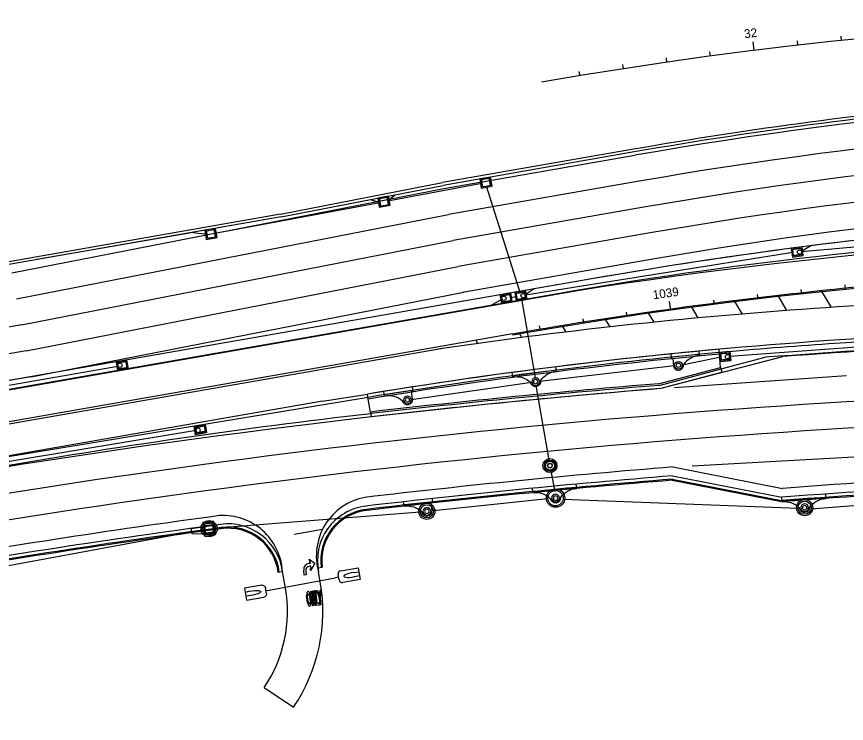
# Model space of a CAD drawing. Extents: x 468143 to 491361, y 1438528 to 1468730.
# Drawn here: x 485954.6 to 486331.8, y 1467266.4 to 1467587.8 of the extents above; entities that cross this region are included whole.
import ezdxf

# ---------------------------------------------------------------- set-up
doc = ezdxf.new("R2010")
doc.units = 0
doc.layers.add('Default', color=7, linetype='Continuous')
doc.layers.add('Xreference_dp', color=7, linetype='Continuous')

# ---------------------------------------------------------------- blocks, each defined once
blk = doc.blocks.new('POINT_DISPLAY')
at = {"layer": 'Default'}
blk.add_line((0, 0), (0, 0), dxfattribs=at)
blk = doc.blocks.new('InltCurb2_35')
at = {"layer": 'Default'}
for p, q in [((-10, 2), (-10, 0)), ((-10, 1.5), (10, 1.5)), ((10, 2), (10, 0))]:
    blk.add_line(p, q, dxfattribs=at)
for radius in [1.75, 1]:
    blk.add_circle((0, 5.5), radius, dxfattribs=at)
for centre, radius, start, end in [((0, 5.5), 2.25, 0, 180), ((-9.85, 12), 10, 269.1432, 319.4677), ((9.85, 12), 10, 220.5323, 270.8568)]:
    blk.add_arc(centre, radius, start, end, dxfattribs=at)
for p in [(0, 7.75), (-1.75, 5.5), (-1.75, 5.5), (-1.62, 4.84), (-1.6, 6.2), (-1.26, 4.28), (-1.22, 6.76), (-0.7, 3.9), (-0.66, 7.12), (0, 7.25), (0, 7.25), (0, 5.5), (0, 5.5), (0.66, 3.88), (0.7, 7.1), (1.22, 4.24), (1.26, 6.72), (1.6, 4.8), (1.62, 6.16), (1.75, 5.5), (1.75, 5.5), (0, 3.75), (0, 3.75), (0, 0), (0, 0)]:
    blk.add_blockref('POINT_DISPLAY', p, dxfattribs=at)
blk = doc.blocks.new('InltCurb7_40')
at = {"layer": 'Default'}
for p, q in [((2.5, 4), (-2.5, 4)), ((-2.5, 4), (-2.5, 0)), ((2.5, 0), (2.5, 4)), ((2.5, 3.25), (-2.5, 3.25)), ((-2.5, 0.75), (2.5, 0.75)), ((-2.5, 0), (2.5, 0))]:
    blk.add_line(p, q, dxfattribs=at)
blk.add_lwpolyline([(-2, 0.5), (2, 0.5), (2, 3.5), (-2, 3.5)], close=True, dxfattribs=at)
blk.add_circle((-1.04, 2.19), 1, dxfattribs=at)
for p in [(0, 4), (-2, 3.5), (-2, 2), (-2, 2), (-2, 0.5), (0, 3.5), (0, 3.5), (0, 2), (0, 2), (0, 0.5), (0, 0.5), (0, 0), (0, 0), (2, 3.5), (2, 2), (2, 2), (2, 0.5)]:
    blk.add_blockref('POINT_DISPLAY', p, dxfattribs=at)
blk = doc.blocks.new('InltCurb1_35')
at = {"layer": 'Default'}
for p, q in [((2.25, 2), (2.25, 5.5)), ((-10, 2), (-10, 0)), ((-10, 1.5), (3, 1.5)), ((3, 2), (2.25, 2)), ((3, 0), (3, 2))]:
    blk.add_line(p, q, dxfattribs=at)
for radius in [1.75, 1]:
    blk.add_circle((0, 5.5), radius, dxfattribs=at)
for centre, radius, start, end in [((0, 5.5), 2.25, 0, 180), ((-9.85, 12), 10, 269.1432, 319.4677)]:
    blk.add_arc(centre, radius, start, end, dxfattribs=at)
for p in [(0, 7.75), (-1.75, 5.5), (-1.75, 5.5), (-1.62, 4.84), (-1.6, 6.2), (-1.26, 4.28), (-1.22, 6.76), (-0.7, 3.9), (-0.66, 7.12), (0, 7.25), (0, 7.25), (0, 5.5), (0, 5.5), (0.66, 3.88), (0.7, 7.1), (1.22, 4.24), (1.26, 6.72), (1.6, 4.8), (1.62, 6.16), (1.75, 5.5), (1.75, 5.5), (0, 3.75), (0, 3.75), (0, 0), (0, 0)]:
    blk.add_blockref('POINT_DISPLAY', p, dxfattribs=at)
blk = doc.blocks.new('InltCurb5')
at = {"layer": 'Default'}
for p, q in [((-2.25, 3.5), (-8, 2.5)), ((-8, 2.5), (-8, 0)), ((-8, 1.5), (2.5, 1.5)), ((-8, 0), (2.5, 0)), ((2.25, 3.5), (-2.25, 3.5)), ((-1.96, 0), (-1.96, 1.5)), ((1.95, 0), (1.95, 1.5)), ((2.25, 2), (2.25, 3.5)), ((2.5, 2), (2.25, 2)), ((2.5, 0), (2.5, 2))]:
    blk.add_line(p, q, dxfattribs=at)
blk.add_lwpolyline([(-1.75, -0.5), (1.75, -0.5), (1.75, 3), (-1.75, 3)], close=True, dxfattribs=at)
for p in [(-1.75, 3), (-1.75, 1.25), (-1.75, 1.25), (0, 3.5), (0, 3), (0, 3), (0, 1.25), (0, 1.25), (1.75, 3), (1.75, 1.25), (1.75, 1.25), (-1.75, -0.5), (0, 0), (0, 0), (0, -0.5), (0, -0.5), (1.75, -0.5)]:
    blk.add_blockref('POINT_DISPLAY', p, dxfattribs=at)
blk = doc.blocks.new('InltBarwll')
at = {"layer": 'Default'}
for p, q in [((2.5, 0), (-2.5, 0)), ((-2.5, 0), (-2.5, -4.25)), ((-2.17, 0), (-2.17, -3.75)), ((-1.83, 0), (-1.83, -3.75)), ((1.83, -3.75), (1.83, 0)), ((2.17, -3.75), (2.17, 0)), ((2.5, -4.25), (2.5, 0)), ((-2.17, -3.75), (2.17, -3.75)), ((1.83, -0.5), (-1.83, -0.5)), ((-2.5, -4.25), (2.5, -4.25))]:
    blk.add_line(p, q, dxfattribs=at)
for p in [(0, 0), (0, 0), (-1.83, -0.5), (-1.83, -2.12), (-1.83, -2.12), (-1.83, -3.75), (0, -0.5), (0, -0.5), (0, -2.12), (0, -2.12), (0, -3.75), (0, -3.75), (1.83, -0.5), (1.83, -2.12), (1.83, -2.12), (1.83, -3.75), (0, -4.25)]:
    blk.add_blockref('POINT_DISPLAY', p, dxfattribs=at)
blk = doc.blocks.new('MESC24RCP4S')
at = {"layer": 'Default'}
for p, q in [((0, 2.45), (0, 3.97)), ((-2.75, -7.03), (-2.75, 0.95)), ((-1.25, 2.45), (1.25, 2.45)), ((2.75, 0.95), (2.75, -7.03)), ((2.75, -7.03), (-2.75, -7.03)), ((-0.98, -4.81), (-0.87, -7.03)), ((0.98, -4.8), (0.86, -7.03))]:
    blk.add_line(p, q, dxfattribs=at)
for centre, start, end in [((-1.25, 0.95), 90, 180), ((1.25, 0.95), 0, 90)]:
    blk.add_arc(centre, 1.5, start, end, dxfattribs=at)
blk.add_ellipse((0, -4), major_axis=(0, 4), ratio=0.25, start_param=4.509879, end_param=8.057799, dxfattribs=at)
for p in [(0, 3.97), (0, 2.45), (0, 0), (0, 0), (0, -7.03)]:
    blk.add_blockref('POINT_DISPLAY', p, dxfattribs=at)
blk = doc.blocks.new('JBottom60Dia')
at = {"layer": 'Default'}
for radius in [3.67, 3, 3]:
    blk.add_circle((0, 0), radius, dxfattribs=at)
for p in [(-2.75, 1.21), (-2.09, 2.15), (-1.13, 2.78), (0, 3), (0, 3), (0, 3), (0, 0), (0, 0), (0, 0), (1.21, 2.75), (2.15, 2.09), (2.78, 1.13), (3, 0), (3, 0), (-3, 0), (-3, 0), (-2.78, -1.13), (-2.15, -2.09), (-1.21, -2.75), (0, -3), (0, -3), (0, -3), (1.13, -2.78), (2.09, -2.15), (2.75, -1.21)]:
    blk.add_blockref('POINT_DISPLAY', p, dxfattribs=at)
blk = doc.blocks.new('JBottom35x50')
at = {"layer": 'Default'}
for p, q in [((2.42, 3.17), (-2.42, 3.17)), ((-2.42, 3.17), (-2.42, -3.17)), ((-1.75, -2.5), (-1.75, 2.5)), ((-1.75, 2.5), (1.75, 2.5)), ((1.75, 2.5), (1.75, -2.5)), ((2.42, -3.17), (2.42, 3.17)), ((-2.42, -3.17), (2.42, -3.17)), ((1.75, -2.5), (-1.75, -2.5))]:
    blk.add_line(p, q, dxfattribs=at)
for p in [(-1.75, 2.5), (-1.75, 0), (-1.75, 0), (0, 2.5), (0, 2.5), (0, 2.5), (0, 0), (0, 0), (0, 0), (1.75, 2.5), (1.75, 0), (1.75, 0), (-1.75, -2.5), (0, -2.5), (0, -2.5), (0, -2.5), (1.75, -2.5)]:
    blk.add_blockref('POINT_DISPLAY', p, dxfattribs=at)
blk = doc.blocks.new('MHCover2')
at = {"layer": 'Default'}
for radius in [2, 1.06, 1]:
    blk.add_circle((0, 0), radius, dxfattribs=at)
for p in [(-2, 0), (-2, 0), (-1.83, 0.81), (-1.39, 1.43), (-0.75, 1.85), (0, 2.5), (0, 2), (0, 2), (0, 0), (0, 0), (0, 0), (0.81, 1.83), (1.43, 1.39), (1.85, 0.75), (2, 0), (2, 0), (-1.85, -0.75), (-1.43, -1.39), (-0.81, -1.83), (0, -2), (0, -2), (0, -2.5), (0.75, -1.85), (1.39, -1.43), (1.83, -0.81)]:
    blk.add_blockref('POINT_DISPLAY', p, dxfattribs=at)
blk = doc.blocks.new('JBottom50Dia')
at = {"layer": 'Default'}
for radius in [3.17, 2.5, 2.5]:
    blk.add_circle((0, 0), radius, dxfattribs=at)
for p in [(-2.29, 1.01), (-1.74, 1.79), (-0.94, 2.32), (0, 2.5), (0, 2.5), (0, 2.5), (0, 0), (0, 0), (0, 0), (1.01, 2.29), (1.79, 1.74), (2.32, 0.94), (2.5, 0), (2.5, 0), (-2.5, 0), (-2.5, 0), (-2.32, -0.94), (-1.79, -1.74), (-1.01, -2.29), (0, -2.5), (0, -2.5), (0, -2.5), (0.94, -2.32), (1.74, -1.79), (2.29, -1.01)]:
    blk.add_blockref('POINT_DISPLAY', p, dxfattribs=at)
blk = doc.blocks.new('JBottom70Dia')
at = {"layer": 'Default'}
for radius in [4.17, 3.5, 3.5]:
    blk.add_circle((0, 0), radius, dxfattribs=at)
for p in [(-3.5, 0), (-3.5, 0), (-3.2, 1.41), (-2.44, 2.51), (-1.32, 3.24), (0, 3.5), (0, 3.5), (0, 3.5), (0, 0), (0, 0), (0, 0), (1.41, 3.2), (2.51, 2.44), (3.24, 1.32), (-3.24, -1.32), (-2.51, -2.44), (-1.41, -3.2), (0, -3.5), (0, -3.5), (0, -3.5), (1.32, -3.24), (2.44, -2.51), (3.2, -1.41), (3.5, 0), (3.5, 0)]:
    blk.add_blockref('POINT_DISPLAY', p, dxfattribs=at)
blk = doc.blocks.new('DARightTurn')
at = {"layer": 'Default'}
for points in [[(2, 2.17), (0, 2.17), (0, 3.17), (2.67, 3.17)], [(5.67, -3.17), (2, -0.5), (4.33, -0.83), (4.33, -0.17)], [(6, -0.17), (6, -0.83), (8.25, -0.5), (5.67, -3.17)]]:
    blk.add_lwpolyline(points, dxfattribs=at)
for centre, radius in [((2, -0.17), 2.33), ((2.67, -0.17), 3.33)]:
    blk.add_arc(centre, radius, 360, 90, dxfattribs=at)
blk = doc.blocks.new('ONLY_5')
at = {"layer": 'Default'}
for p, q in [((1.94, 3.96), (6.06, 3.96)), ((6.06, 1.96), (1.94, 1.96)), ((5.6, 3.63), (2.4, 3.63)), ((2.4, 2.29), (5.6, 2.29))]:
    blk.add_line(p, q, dxfattribs=at)
for points in [[(0, -0.12), (0, 0.21), (5, 1.13), (0, 1.13), (0, 1.46), (8, 1.46), (8, 1.13), (2.9, 0.21), (8, 0.21), (8, -0.12), (0, -0.12)], [(1.33, -2.12), (0, -2.12), (0, -0.79), (8, -0.79), (8, -1.12), (1.33, -1.12), (1.33, -2.12)], [(8, -3.96), (3.67, -3.12), (0, -3.12), (0, -2.79), (3.67, -2.79), (8, -1.96), (8, -2.3), (4.57, -2.96), (8, -3.62), (8, -3.96)]]:
    blk.add_lwpolyline(points, dxfattribs=at)
for major_axis, ratio, start_param, end_param in [((4, 0), 0.291667, 2.111896, 4.171289), ((2.67, 0), 0.3125, 2.214297, 4.068888), ((2.67, 0), 0.3125, 5.35589, 7.210481), ((4, 0), 0.291667, 5.253489, 7.312882)]:
    blk.add_ellipse((4, 2.96), major_axis=major_axis, ratio=ratio, start_param=start_param, end_param=end_param, dxfattribs=at)

msp = doc.modelspace()

# ---------------------------------------------------------------- linework, layer by layer
at = {"layer": 'Xreference_dp'}
for p, q in [((486309.72, 1467574.76), (486309.49, 1467576.75)), ((486329.6, 1467576.94), (486329.39, 1467578.93)), ((486289.86, 1467572.39), (486289.37, 1467576.36)), ((486250.22, 1467567.04), (486249.94, 1467569.02)), ((486270.03, 1467569.81), (486269.76, 1467571.8)), ((486230.44, 1467564.07), (486230.14, 1467566.05)), ((486210.7, 1467560.9), (486210.37, 1467562.88)), ((486235.08, 1467527.45), (486148.22, 1467512.29)), ((486235.29, 1467526.22), (486148.44, 1467511.06)), ((486148.72, 1467509.58), (486235.55, 1467524.75)), ((486162.06, 1467513.43), (486148.44, 1467511.06)), ((486237.61, 1467512.92), (486150.9, 1467497.78)), ((485952.39, 1467471.23), (486148.72, 1467509.58)), ((486074.59, 1467497.91), (486148.19, 1467512.28)), ((486074.82, 1467496.68), (486148.43, 1467511.05)), ((486123.35, 1467503.95), (486166.12, 1467511.99)), ((486126.58, 1467506.79), (486148.43, 1467511.05)), ((486183.54, 1467462.37), (486168.2, 1467510.7)), ((486123.35, 1467503.95), (486126.58, 1467506.79)), ((486044.71, 1467489.26), (486119.74, 1467503.32)), ((486074.82, 1467496.68), (486115.49, 1467504.62)), ((486115.49, 1467504.62), (486119.74, 1467503.32)), ((486074.59, 1467497.91), (485941.79, 1467474.71)), ((485954.57, 1467459.43), (486150.9, 1467497.78)), ((486239.68, 1467501.1), (486153.08, 1467485.98)), ((486074.83, 1467496.68), (485942.01, 1467473.48)), ((486074.83, 1467496.68), (486046.14, 1467491.67)), ((486311.43, 1467481.03), (486438.13, 1467491.8)), ((486034.83, 1467489.69), (485963.73, 1467477.28)), ((486034.83, 1467489.69), (486041.05, 1467488.88)), ((486241.74, 1467489.28), (486155.26, 1467474.18)), ((485956.75, 1467447.63), (486153.08, 1467485.98)), ((486315.67, 1467483.59), (486311.43, 1467481.03)), ((486307.46, 1467480.51), (486185.84, 1467461.06)), ((486243.81, 1467477.46), (486157.33, 1467462.36)), ((485958.93, 1467435.83), (486155.26, 1467474.18)), ((486215.08, 1467468.38), (485248.96, 1467299.66)), ((486215.08, 1467468.38), (486189.9, 1467463.99)), ((486189.9, 1467463.99), (486185.77, 1467461.23)), ((486311.51, 1467461.67), (486311.29, 1467463.66)), ((486331.4, 1467463.77), (486331.2, 1467465.76)), ((486201.33, 1467461.92), (485249.64, 1467295.72)), ((486209.52, 1467463.1), (485249.69, 1467295.48)), ((485961.12, 1467424.03), (486157.92, 1467462.47)), ((486179.07, 1467460.07), (486181.83, 1467460.55)), ((486291.64, 1467459.39), (486291.4, 1467461.38)), ((486304.73, 1467454.15), (486300.7, 1467460.96)), ((486324.96, 1467455.57), (486320.48, 1467463.14)), ((486170.14, 1467456.47), (486032.77, 1467432.49)), ((486170.14, 1467456.47), (486175.13, 1467459.38)), ((486184.06, 1467459.41), (486190.26, 1467423.56)), ((486251.97, 1467454.26), (486251.42, 1467458.22)), ((486264.43, 1467450.78), (486261.32, 1467456.04)), ((486271.79, 1467456.92), (486271.54, 1467458.9)), ((486284.55, 1467452.55), (486280.98, 1467458.59)), ((486232.18, 1467451.41), (486231.88, 1467453.39)), ((486244.37, 1467448.82), (486241.72, 1467453.31)), ((486212.41, 1467448.37), (486212.1, 1467450.34)), ((486224.36, 1467446.69), (486222.17, 1467450.4)), ((485956.75, 1467447.63), (485244.83, 1467323.31)), ((486192.67, 1467445.14), (486192.34, 1467447.11)), ((486204.34, 1467444.37), (486202.61, 1467447.3)), ((486179.94, 1467443.47), (486145.57, 1467437.47)), ((486184.27, 1467441.85), (486183, 1467444)), ((486145.57, 1467437.47), (485252.14, 1467281.44)), ((486164.27, 1467439.17), (486163.43, 1467440.58)), ((486278.67, 1467433.43), (486351.69, 1467438.74)), ((486145.74, 1467436.48), (485252.31, 1467280.46)), ((485958.93, 1467435.83), (485278.59, 1467317.02)), ((486247, 1467418.64), (486302.96, 1467433.23)), ((486274.08, 1467434.27), (486273.88, 1467436.51)), ((486274.62, 1467428.3), (486274.08, 1467434.27)), ((486257.19, 1467429.41), (486274.69, 1467433.07)), ((486274.81, 1467427.57), (486294.82, 1467432.87)), ((485936.01, 1467417.62), (486000.6, 1467428.9)), ((486192.22, 1467422.05), (486253.71, 1467429.07)), ((486246.42, 1467420.82), (486274.62, 1467428.3)), ((486246.61, 1467420.09), (486274.81, 1467427.57)), ((486247, 1467418.64), (486275.2, 1467426.12)), ((486274.62, 1467428.3), (486275.2, 1467426.12)), ((485961.12, 1467424.03), (485248.96, 1467299.66)), ((486253.68, 1467419.11), (486331.79, 1467424.59)), ((486133.95, 1467413.75), (486188.75, 1467421.6)), ((486196.68, 1467386.1), (486190.72, 1467420.09)), ((486114.34, 1467414.65), (485947.06, 1467387.06)), ((486093.61, 1467412.91), (486114.1, 1467416.13)), ((486114.46, 1467413.91), (486114.1, 1467416.13)), ((486093.61, 1467412.91), (485254.76, 1467266.42)), ((486115.44, 1467407.99), (486114.46, 1467413.91)), ((486115.44, 1467407.99), (486115.7, 1467405.76)), ((485941.78, 1467384.11), (486036.13, 1467399.73)), ((486261.71, 1467383.58), (486341.48, 1467388)), ((486197.46, 1467381.16), (486199.19, 1467371.82)), ((486252.93, 1467383.01), (486302.67, 1467373.29)), ((486252.59, 1467376.96), (486302.31, 1467367.25)), ((486252.62, 1467377.46), (486302.34, 1467367.75)), ((486252.71, 1467378.97), (486302.43, 1467369.27)), ((486196.08, 1467368.51), (486144.04, 1467363.14)), ((486309.81, 1467364.2), (486203, 1467368.16)), ((486376.27, 1467368.36), (486315.74, 1467363.89)), ((486043.81, 1467355.17), (486138.07, 1467362.56)), ((485950.19, 1467337.99), (486040.34, 1467354.7)), ((486093.59, 1467354.52), (486080.7, 1467352.29)), ((486075.49, 1467335.31), (486073.5, 1467335.06)), ((486076.78, 1467327.97), (486075.47, 1467335.46)), ((486076.78, 1467327.97), (486075.47, 1467335.46)), ((486091.51, 1467337.22), (486093.5, 1467337.47)), ((486069.43, 1467327.05), (486099.42, 1467332.6)), ((486092.64, 1467330.74), (486091.87, 1467335.12)), ((486092.64, 1467330.74), (486091.87, 1467335.12)), ((486067.15, 1467282.73), (486080.5, 1467273.74))]:
    msp.add_line(p, q, dxfattribs=at)
for centre, radius, start, end in [((486537.7, 1465584.94), 2002.84, 65.37329, 99.90546), ((486576.17, 1465574.26), 1980, 80.60151, 99.90595), ((486576.17, 1465574.26), 1982.75, 95.2178, 99.90595), ((486576.17, 1465574.26), 1981.5, 94.91867, 99.90595), ((486576.17, 1465574.26), 1968, 80.60151, 99.90595), ((486576.17, 1465574.26), 1956, 80.60151, 99.90595), ((486576.17, 1465574.26), 1944, 80.59814, 99.90595), ((486576.17, 1465574.26), 1932, 80.72286, 99.90595), ((486597.77, 1465276.99), 2224.56, 94.1553, 99.90595), ((486597.77, 1465276.99), 2224.56, 95.10723, 97.2853), ((486531.6, 1465570.76), 1919.78, 92.82593, 99.95282), ((486541.29, 1465374.28), 2115, 79.49165, 99.02499), ((486597.77, 1465276.99), 2224.56, 97.62176, 99.90595), ((486541.29, 1465374.28), 2100, 65.36712, 99.90595), ((486541.29, 1465374.28), 2100.5, 95.46596, 99.90595), ((486587.77, 1463535.87), 3928.5, 91.44817, 93.86982), ((486469.37, 1465245.19), 2215.09, 93.79821, 98.33668), ((486587.77, 1463535.87), 3913.5, 91.44817, 93.86982), ((486587.77, 1463535.87), 3912, 91.44817, 93.86982), ((486587.77, 1463535.87), 3908, 91.44817, 94.29909), ((486587.77, 1463535.87), 3907.75, 91.44817, 94.17965), ((486472.13, 1465245.46), 2200, 93.86982, 99.36603), ((486472.13, 1465245.46), 2198.5, 93.86982, 95.17011), ((486472.13, 1465245.46), 2200, 95.17011, 99.36603), ((486472.13, 1465245.46), 2198.5, 95.17011, 99.36603), ((486472.13, 1465245.46), 2197.75, 95.17011, 99.36603), ((486162.71, 1467337.93), 100, 98.3367, 99.7661), ((486562.18, 1463531.4), 3900, 94.6355, 99.90595), ((486562.18, 1463531.4), 3888, 90.64932, 99.90595), ((486562.18, 1463531.4), 3902.25, 94.63891, 96.5738), ((486562.18, 1463531.4), 3901.5, 94.63777, 96.5738), ((486562.18, 1463531.4), 3900, 94.6355, 96.5738), ((486562.18, 1463531.4), 3876, 90.64932, 99.90595), ((486460.61, 1464412.8), 3014.26, 96.5738, 99.90595), ((486562.18, 1463531.4), 3864, 94.59044, 96.67651), ((486587.77, 1463535.87), 3848, 91.44817, 94.24896), ((486562.18, 1463531.4), 3860, 94.5986, 96.67651), ((486562.18, 1463531.4), 3858.5, 94.60166, 96.67651), ((486562.18, 1463531.4), 3858, 94.60268, 96.67651), ((486587.77, 1463535.87), 3842, 91.44817, 94.26097), ((486587.77, 1463535.87), 3842.5, 91.44817, 94.25997), ((486587.77, 1463535.87), 3844, 91.44817, 94.25697), ((486117.88, 1467342.59), 27.06, 100.526, 196.0234), ((486116.31, 1467340.39), 25, 96.6765, 192.1739), ((486116.31, 1467340.39), 23.5, 96.6765, 187.2917), ((486116.31, 1467340.39), 23, 96.6765, 187.2917), ((486562.18, 1463531.4), 3864, 97.66461, 99.90595), ((486048.44, 1467333.85), 27.07, 3.4109, 93.4296), ((486562.18, 1463531.4), 3860, 97.66461, 99.90595), ((486562.18, 1463531.4), 3858.5, 97.66461, 99.90595), ((486562.18, 1463531.4), 3858, 97.66461, 99.90595), ((486050.69, 1467332.14), 25, 7.646, 97.6646), ((486050.69, 1467332.14), 23.5, 7.2986, 97.6646), ((486050.69, 1467332.14), 23, 7.2986, 97.6646), ((486015.75, 1467317.32), 61.95, 326.0609, 9.9059), ((486015.75, 1467317.32), 61.95, 326.0609, 9.9059), ((486015.75, 1467317.32), 78.05, 326.0609, 9.9059), ((486015.75, 1467317.32), 78.05, 326.0609, 9.9059)]:
    msp.add_arc(centre, radius, start, end, dxfattribs=at)

# ---------------------------------------------------------------- block references
for name, p, rotation in [('InltBarwll', (486167.56, 1467514.39), 9.9059481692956), ('InltBarwll', (486121.18, 1467505.73), 9.9059481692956), ('InltBarwll', (486042.54, 1467491.04), 9.9059481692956), ('InltCurb7_40', (486309.19, 1467482.75), -172.5785641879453), ('InltCurb7_40', (486177.45, 1467457.75), 9.9059481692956), ('InltCurb7_40', (486183.46, 1467462.86), -170.0940518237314), ('InltCurb1_35', (486254.92, 1467434.71), -174.45823543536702), ('InltCurb7_40', (486276.5, 1467435.24), -174.8950663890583), ('InltCurb7_40', (486002.92, 1467427.27), 9.9059481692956), ('JBottom50Dia', (486197.03, 1467383.62), 99.83664176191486), ('MHCover2', (486197.03, 1467383.62), 99.83664176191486), ('JBottom70Dia', (486199.57, 1467368.84), 95.42949533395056), ('JBottom60Dia', (486141.06, 1467362.85), 75.04782274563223), ('JBottom60Dia', (486312.8, 1467364.5), 75.04782274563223), ('JBottom60Dia', (486042.08, 1467354.94), 75.04782274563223), ('JBottom35x50', (486042.08, 1467354.94), 7.810771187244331), ('MESC24RCP4S', (486103.33, 1467333.28), 99.90594816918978)]:
    msp.add_blockref(name, p, dxfattribs=dict(at, rotation=rotation))
for name, p, yscale, rotation in [('InltCurb2_35', (486189.77, 1467427.28), -1.0000000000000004, 7.50975641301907), ('InltCurb1_35', (486131.37, 1467418.91), -1.0000000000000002, 8.873947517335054), ('InltCurb7_40', (486037.78, 1467402.03), -1.0000000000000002, 9.366028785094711), ('InltCurb2_35', (486199.04, 1467374.31), -1.0000000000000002, 5.478455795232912), ('InltCurb2_35', (486312.41, 1467369.98), -1.0000000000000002, 4.107907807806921), ('InltCurb1_35', (486140.46, 1467368.32), -1.0000000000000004, 6.255201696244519), ('InltCurb5', (486041.91, 1467356.17), -0.9999999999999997, 7.81077118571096), ('MESC24RCP4S', (486065.52, 1467326.36), -1.0000000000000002, 99.9059481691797)]:
    msp.add_blockref(name, p, dxfattribs=dict(at, yscale=yscale, rotation=rotation))
at = {"layer": 'Xreference_dp', "xscale": 0.8435617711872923, "yscale": 0.8435617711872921, "rotation": 96.68864777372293}
for name, p in [('DARightTurn', (486088.01, 1467334.19)), ('ONLY_5', (486090.27, 1467319.99))]:
    msp.add_blockref(name, p, dxfattribs=at)

# ---------------------------------------------------------------- texts
at = {"layer": 'Xreference_dp'}
for s, rotation, p in [('32', 7.1082, (486285.56, 1467577.9)), ('1039', 7.919, (486244.03, 1467459.21))]:
    msp.add_text(s, height=4, rotation=rotation, dxfattribs=at).set_placement(p)

doc.saveas('drawing.dxf')
